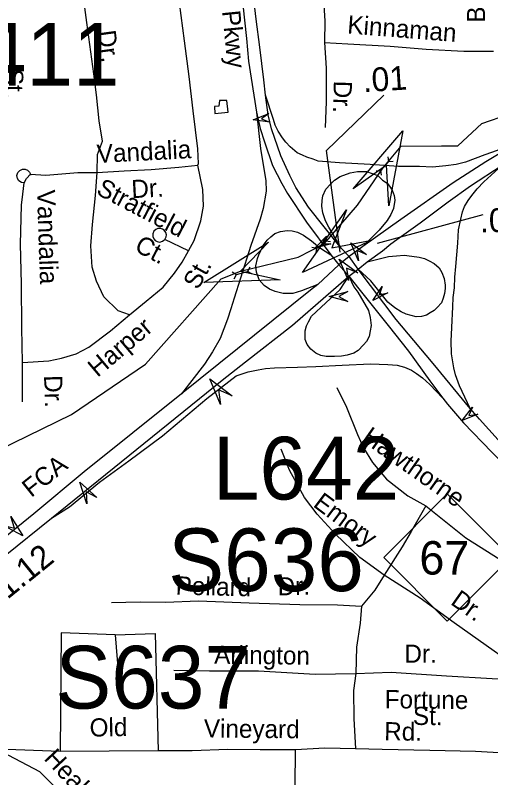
# Model space of a CAD drawing. Extents: x 1547597 to 1699558, y 810033 to 920809.
# Drawn here: x 1612140 to 1614630, y 849367 to 853357 of the extents above; entities that cross this region are included whole.
import ezdxf

# ---------------------------------------------------------------- set-up
doc = ezdxf.new("R2010")
doc.units = 0
for name, color, linetype in [('Exist Hydrographic Creek Single Shore', 7, 'Continuous'), ('Exist Hydrographic Misc Water Feature', 7, 'Continuous'), ('Exist Road Non-System Type 51', 7, 'Continuous'), ('Exist Road Non-System Type 51 Label', 7, 'Continuous'), ('Exist Road Primary Interstate Divided Center Attributed', 7, 'Continuous'), ('Exist Road Primary Interstate Label', 7, 'Continuous'), ('Exist Road Primary Interstate Mileage Hundredths English Label', 7, 'Continuous'), ('Exist Road Primary Interstate Ramp 1 Lane Attributed', 7, 'Continuous'), ('Exist Road Primary Interstate Structure Cantilever Sign Attributed CELL', 7, 'Continuous'), ('Exist Road Primary Interstate Structure Cantilever Sign Number Label', 7, 'Continuous'), ('Exist Road Primary Interstate Structure Ovrhead Sign Attributed CELL', 7, 'Continuous'), ('Exist Road Primary Interstate Structure Ovrhead Sign Number Label', 7, 'Continuous'), ('Exist Road Primary NC Divided Attributed', 7, 'Continuous'), ('Exist Road Primary NC Label', 7, 'Continuous'), ('Exist Road Primary NC Service Mileage Hundredths English Label', 7, 'Continuous'), ('Exist Road Primary NC Shield CELL', 7, 'Continuous'), ('Exist Road Primary NC Shield Number Label', 7, 'Continuous'), ('Exist Road Secondary Structure Culvert Attributed CELL', 7, 'Continuous'), ('Exist Road Secondary Structure Culvert CELL', 7, 'Continuous'), ('Exist Road Secondary Structure Culvert Number Label', 7, 'Continuous'), ('Exist Road Secondary Structure Standard Bridge Attributed CELL', 7, 'Continuous')]:
    doc.layers.add(name, color=color, linetype=linetype)

msp = doc.modelspace()

# ---------------------------------------------------------------- linework, layer by layer
at = {"layer": 'Exist Hydrographic Creek Single Shore'}
msp.add_lwpolyline([(1611594.1, 850857.9), (1612435.7, 851267.3), (1612822.7, 851531.9), (1613218.5, 851977.1), (1613319.3, 852016.9), (1613622.3, 852090.4), (1613757.8, 852160.1), (1613932.3, 852362.2), (1614064.9, 852556.6), (1614161.3, 852672.3), (1614372.7, 852674), (1614458.3, 852674), (1614584.2, 852789.9), (1615148.9, 852985.6), (1615306.6, 853204), (1615898.7, 853406.3), (1616283.8, 853510.1), (1617321.6, 853814.1), (1617885.8, 853975.5), (1618594.7, 854297), (1618697.7, 854345.4)], dxfattribs=at)
at = {"layer": 'Exist Hydrographic Misc Water Feature'}
msp.add_lwpolyline([(1613254.9, 852850.4), (1613248, 852911.2), (1613209.4, 852909.8), (1613207, 852880.6), (1613184.3, 852879.1), (1613185, 852843.4), (1613254.9, 852850.4)], dxfattribs=at)
at = {"layer": 'Exist Road Non-System Type 51'}
for p, q in [((1613048.2, 852123.9), (1612923.5, 852184)), ((1612178.9, 851334.6), (1612178.9, 851540.3))]:
    msp.add_line(p, q, dxfattribs=at)
for points in [[(1612568.7, 852534.1), (1612571.1, 852628.7), (1612597.4, 852697.7), (1612579.3, 852804.2), (1612565.9, 852940.3), (1612551.9, 853050.5), (1612514.9, 853319), (1612472.7, 853633.6), (1612437.8, 853908), (1612402.5, 854158.5), (1612362.1, 854455.1), (1612344.6, 854645.6)], [(1613680.2, 854248.2), (1613697.3, 854054), (1613721.4, 853801.8), (1613750.7, 853491.6), (1613762.2, 853327.5), (1613760.5, 853213.6)], [(1613096.5, 852572.7), (1613100.7, 852580.7), (1613096, 852658.6), (1613071.9, 852857), (1613051.5, 853035.7), (1613026.7, 853223.5), (1613000.3, 853422), (1612976.7, 853660.4), (1612961.3, 853800.6)], [(1613760.5, 853213.6), (1613768.3, 853079.6), (1613767.8, 852903.7), (1613763.7, 852769.9)], [(1613760.5, 853213.6), (1613882.2, 853207.8), (1614103.9, 853194.5), (1614291.5, 853179.7), (1614489.1, 853168.8), (1614645, 853168.5)], [(1612187.6, 852480.5), (1612173, 852481.4), (1612159.8, 852490.6), (1612151.8, 852501.8), (1612149.3, 852517.9), (1612153.4, 852533.4), (1612164.1, 852544.8), (1612177.8, 852550.9), (1612192, 852550.8), (1612205.5, 852545.3), (1612215.1, 852535.5), (1612219.9, 852524.8), (1612220.2, 852519.8)], [(1612568.7, 852534.1), (1612710.3, 852541.8), (1612852.3, 852549.1), (1612996.4, 852562.6), (1613096.5, 852572.7)], [(1613048.2, 852123.9), (1613077.3, 852177.3), (1613113, 852280.4), (1613126.6, 852358.2), (1613122.1, 852444.4), (1613096.5, 852572.7)], [(1612187.6, 852480.5), (1612200, 852503.4), (1612219.9, 852524.8)], [(1612219.9, 852524.8), (1612300.4, 852519.5), (1612468.4, 852534.3), (1612568.7, 852534.1)], [(1612738.4, 851789.8), (1612679.8, 851810.3), (1612603.5, 851883.5), (1612565.1, 851966.1), (1612542.8, 852038.3), (1612537.1, 852150.3), (1612544.8, 852261.5), (1612561.5, 852413.2), (1612568.7, 852534.1)], [(1612178.9, 851540.3), (1612175.3, 851720.7), (1612172.4, 851950.9), (1612167.7, 852159.8), (1612173.5, 852363), (1612180.3, 852420.9), (1612187.6, 852480.5)], [(1612923.5, 852184), (1612927.2, 852189.8), (1612930.8, 852197.9), (1612931.6, 852208.5), (1612928.7, 852220.8), (1612920.9, 852231.7), (1612911.6, 852238.1), (1612901.1, 852241.7), (1612886.7, 852240.8), (1612876.4, 852235.8), (1612866.6, 852227), (1612860.9, 852213.3), (1612860.6, 852199.9), (1612865.6, 852187.2), (1612873.2, 852178.7), (1612883.9, 852172.2), (1612897.8, 852170.3), (1612910.9, 852173.9), (1612919.2, 852179.1), (1612923.5, 852184)], [(1612738.4, 851789.8), (1612825.5, 851860), (1612914.9, 851934.3), (1612974.2, 852007.3), (1613015.2, 852064.5), (1613048.2, 852123.9)], [(1612178.9, 851540.3), (1612315.8, 851548.7), (1612382, 851562.9), (1612458.9, 851584.9), (1612525.5, 851619.8), (1612638.9, 851705.5), (1612738.4, 851789.8)], [(1613824.7, 851408.5), (1613874.8, 851305.7), (1613932.2, 851162.6), (1613964.8, 851094.1), (1614011.1, 851017.3), (1614083.7, 850930.2), (1614196.1, 850843.1), (1614289.6, 850789.6)], [(1614072.1, 850427.3), (1613944.1, 850519.2), (1613817.9, 850641.9), (1613720.5, 850746.5), (1613655.6, 850833.1), (1613576.3, 850977.4), (1613533, 851085.7)], [(1614289.6, 850789.6), (1614213.4, 850655.3), (1614166.4, 850576.1), (1614072.1, 850427.3)], [(1614289.6, 850789.6), (1614499.9, 850622.6), (1614679.1, 850508.9), (1614923.7, 850344.4), (1615083.8, 850219.7)], [(1614072.1, 850427.3), (1614022.9, 850349.3), (1613953.4, 850264.5)], [(1614855.5, 849882.8), (1614648.3, 850030.5), (1614439.2, 850178.2), (1614260.7, 850307.5), (1614072.1, 850427.3)], [(1612645.3, 850284.4), (1612795.2, 850287.6), (1612926.8, 850285.3), (1613100.8, 850293.2), (1613365.5, 850282.3), (1613630, 850274.4), (1613827.7, 850272.8), (1613953.4, 850264.5)], [(1613953.4, 850264.5), (1613945.8, 850176.8), (1613927.4, 850051.1), (1613923, 849913.3)], [(1612380.1, 850126.2), (1612376.5, 849505.5)], [(1612663, 850115.3), (1612380.1, 850126.2)], [(1612663, 850115.3), (1612873.3, 850122.6)], [(1612663, 850115.3), (1612681.1, 849901.2)], [(1612873.3, 850122.6), (1612888.7, 849508.1)], [(1612970.2, 849930.2), (1613157.8, 849926.9), (1613413.5, 849926.1), (1613711, 849909.2), (1613923, 849913.3)], [(1613923, 849913.3), (1613911.4, 849823.5), (1613912.6, 849677.6), (1613921.6, 849519.5)], [(1613923, 849913.3), (1614108.9, 849919.9), (1614398.5, 849901), (1614637.9, 849886.4), (1614855.5, 849882.8)], [(1611909.7, 849523), (1612105.3, 849484.7), (1612266.9, 849399.5), (1612424.2, 849242.1), (1612589.7, 849074.1)], [(1612376.5, 849505.5), (1611909.7, 849523)], [(1613607.9, 849513.1), (1613423.5, 849512.8), (1613253.4, 849514.7), (1613066.1, 849508.1), (1612888.7, 849508.1)], [(1613616.3, 848999.2), (1613606.9, 849135.3), (1613606.3, 849323.2), (1613607.9, 849513.1)], [(1613921.6, 849519.5), (1613761.8, 849522.4), (1613607.9, 849513.1)], [(1615139.8, 849441.5), (1615073.2, 849463.1), (1615051.3, 849474.8), (1614934, 849486.3), (1614796.8, 849491.6), (1614550.7, 849503.9), (1614311.1, 849510.4), (1614061.4, 849514.9), (1613921.6, 849519.5)], [(1612888.7, 849508.1), (1612376.5, 849505.5)]]:
    msp.add_lwpolyline(points, dxfattribs=at)
at = {"layer": 'Exist Road Primary Interstate Divided Center Attributed'}
for points in [[(1614990.7, 852819.7), (1614604, 852590), (1614433.5, 852479), (1614160, 852287.2), (1613959.7, 852146)], [(1613983, 852066.1), (1614062.6, 852124.5), (1614107.8, 852160.5), (1614137.7, 852183.6), (1614260.8, 852270), (1614407.1, 852380.7), (1614524.1, 852463.9), (1614690.2, 852571.5)], [(1613959.7, 852146), (1613888.2, 852094.4)], [(1613888.2, 852094.4), (1613834.3, 852051.2)], [(1613936.5, 852028), (1613983, 852066.1)], [(1613834.3, 852051.2), (1613724, 851947.1)], [(1613886.3, 851991.7), (1613936.5, 852028)], [(1612330.6, 850725.5), (1613224.7, 851447.9), (1613346.8, 851542.9), (1613591.4, 851734.7), (1613886.3, 851991.7)], [(1613724, 851947.1), (1613686.7, 851918.9), (1613010.2, 851375.8)], [(1613010.2, 851375.8), (1612501.3, 850967.3), (1612238.6, 850748.3), (1611807.5, 850398.9), (1611455.2, 850113.6), (1611165.3, 849893.8), (1610880.9, 849686.6)], [(1609818, 848863.7), (1610951.8, 849650.5), (1611075.2, 849735.8), (1611208.1, 849832), (1611360.5, 849948.2), (1611508.2, 850064.4), (1611742.4, 850253.5), (1612088.1, 850529.5), (1612330.6, 850725.5)]]:
    msp.add_lwpolyline(points, dxfattribs=at)
at = {"layer": 'Exist Road Primary Interstate Mileage Hundredths English Label'}
msp.add_lwpolyline([(1613841.6, 852117.4), (1613770.3, 852649.7), (1614070.2, 852938.4)], dxfattribs=at)
at = {"layer": 'Exist Road Primary Interstate Ramp 1 Lane Attributed'}
for points in [[(1614990.7, 852819.7), (1614663.6, 852648.7), (1614599.9, 852627.1), (1614498.7, 852588.7), (1614450, 852575.6), (1614395.6, 852568.1), (1614324.4, 852562.5), (1614256.7, 852564.9), (1614147.1, 852564.9), (1613998.1, 852575.2), (1613838.8, 852585.1), (1613726.5, 852593.4), (1613700.4, 852603.7), (1613667, 852613.9), (1613643.8, 852624.1), (1613616.8, 852637.1), (1613580.6, 852667.8), (1613557.3, 852692.9), (1613539.7, 852716.1), (1613516.4, 852749.6), (1613500.6, 852782.1), (1613493.2, 852810.9), (1613450.5, 852939.1)], [(1613404, 852849), (1613424.4, 852659.4), (1613442.1, 852553.5), (1613452.3, 852492.2), (1613455.1, 852435.5), (1613439.3, 852346.3), (1613423.5, 852290), (1613373.5, 852152.1), (1613320.1, 851980.6), (1613286.4, 851876.6), (1613269.6, 851820.4), (1613252.7, 851767), (1613233.1, 851716.4), (1613213.4, 851665.8), (1613174.1, 851595.5), (1613131.9, 851530.8), (1613010.2, 851375.8)], [(1614522.4, 851299.9), (1614466.2, 851418.6), (1614445.7, 851474.8), (1614436.9, 851512), (1614425.3, 851584.9), (1614423, 851653.9), (1614424.4, 851686.9), (1614426.7, 851723.6), (1614431, 851830.6), (1614433.4, 851880.4), (1614440.5, 851930.2), (1614442.8, 851987.1), (1614447.6, 852041.6), (1614457, 852164.8), (1614461.8, 852233.6), (1614473.6, 852290.4), (1614483.1, 852328.4), (1614492.6, 852356.8), (1614511.5, 852387.6), (1614530.5, 852413.7), (1614558.9, 852449.2), (1614594.4, 852484.8), (1614690.2, 852571.5)], [(1613847.3, 852137.2), (1613783.2, 852247.7), (1613764.6, 852280.3), (1613750.7, 852322.7), (1613745, 852358.3), (1613746.9, 852388.1), (1613750.7, 852412.6), (1613767.1, 852446.9), (1613790.3, 852473.6), (1613812, 852493.1), (1613842.6, 852513.5), (1613893.7, 852532.1), (1613931.8, 852538.6), (1613979.2, 852538.6), (1614038.7, 852518.2), (1614063.8, 852493.1), (1614087, 852477.3), (1614100, 852462.4), (1614114.9, 852442), (1614125.1, 852414.1), (1614127.9, 852389), (1614120.5, 852345.3), (1614107.5, 852314.7), (1614088, 852283.1), (1614046.5, 852231.5), (1613959.7, 852146)], [(1613724, 851947.1), (1613638.8, 851914), (1613594.4, 851900.7), (1613542.8, 851901.1), (1613501.2, 851911.1), (1613471.1, 851924), (1613443.7, 851943.6), (1613418.5, 851973.1), (1613403.7, 852013), (1613400.8, 852046.4), (1613408.4, 852083.4), (1613416.6, 852103.3), (1613426.6, 852126.3), (1613441, 852153.6), (1613459.6, 852179.4), (1613478.2, 852198), (1613499.8, 852215.3), (1613529.9, 852225.3), (1613564.3, 852231), (1613590.1, 852228.2), (1613618.8, 852221), (1613650.3, 852205.2), (1613691.9, 852176.5), (1613733.5, 852140.7), (1613793.4, 852102.8)], [(1613983, 852066.1), (1614059.1, 852086.6), (1614094.6, 852093.7), (1614137.3, 852098.5), (1614177.5, 852100.8), (1614217.8, 852096.1), (1614255.7, 852091.4), (1614284.1, 852084.2), (1614307.8, 852072.4), (1614333.9, 852058.2), (1614359.9, 852034.5), (1614374.1, 852010.8), (1614386, 851980), (1614392.1, 851943.8), (1614390.7, 851927.8), (1614388.3, 851901.7), (1614381.2, 851875.7), (1614371.8, 851852), (1614350.4, 851828.3), (1614333.9, 851811.7), (1614312.6, 851799.8), (1614293.6, 851788), (1614267.5, 851780.9), (1614239.1, 851778.5), (1614214.3, 851785.7), (1614187.4, 851792.2), (1614161.8, 851804.7), (1614128.4, 851825.1), (1614091.7, 851855.8), (1614001.5, 851966.6), (1613936.5, 852028)], [(1613886.3, 851991.7), (1613912.8, 851935.6), (1613933.7, 851907.2), (1613989.5, 851811.4), (1613999.7, 851774.7), (1614003.9, 851733.8), (1613999.7, 851705.5), (1613993.6, 851676.7), (1613979.2, 851649.3), (1613964.8, 851631.9), (1613936.4, 851603.5), (1613912.8, 851588.4), (1613877.9, 851578.9), (1613849.6, 851572.8), (1613812.4, 851571.4), (1613768.1, 851571.6), (1613739.8, 851576.9), (1613715, 851589.3), (1613688.4, 851608.8), (1613668.9, 851633.6), (1613658.3, 851660.2), (1613658.3, 851685), (1613658.3, 851706.3), (1613665.4, 851731.1), (1613676, 851752.4), (1613691.9, 851782.5), (1613842.6, 851921.6), (1613886.3, 851991.7)], [(1612330.6, 850725.5), (1612424.5, 850784.1), (1612582.5, 850913.7), (1612735.8, 851026.2), (1612911.5, 851155.4), (1613143.8, 851351), (1613297.1, 851470.7), (1613360.4, 851491.1), (1613412.5, 851502.3), (1613451.5, 851507.9), (1613498, 851511.6), (1613617.8, 851514.9), (1613713.9, 851519.1), (1613851.6, 851526.5), (1614000.4, 851532.1), (1614091.6, 851530.2), (1614139.9, 851526.5), (1614179, 851515.3), (1614214.4, 851500.4), (1614242.3, 851481.8), (1614272, 851459.5), (1614311.1, 851424.1), (1614379.4, 851353.8)]]:
    msp.add_lwpolyline(points, dxfattribs=at)
at = {"layer": 'Exist Road Primary Interstate Structure Cantilever Sign Attributed CELL'}
msp.add_lwpolyline([(1613882.3, 851859.2), (1613783.4, 851885.7), (1613882.3, 851912.2), (1613834.6, 851885.7)], close=True, dxfattribs=at)
at = {"layer": 'Exist Road Primary Interstate Structure Ovrhead Sign Attributed CELL'}
for points in [[(1613473.6, 852797.6), (1613386.5, 852809), (1613467.6, 852842.6), (1613430, 852814.8)], [(1613793.2, 852161.4), (1613708.7, 852137.5), (1613769.9, 852200.4), (1613746.4, 852160)], [(1613938.6, 852072.6), (1613898.1, 852166.6), (1613980.2, 852105.4), (1613929.8, 852126.4)], [(1614091.9, 851903.7), (1614013.3, 851864.7), (1614061.9, 851937.8), (1614046.2, 851893.7)], [(1613216, 851319.7), (1613159.8, 851454.8), (1613276, 851365.9), (1613204.4, 851396.8)], [(1614562.4, 851269.8), (1614480.9, 851237.1), (1614535.1, 851306.2), (1614516.1, 851263.4)], [(1612514.7, 850800.3), (1612479.1, 850914.3), (1612566.9, 850833.4), (1612511, 850863.9)], [(1612117.6, 850734), (1612180.6, 850632.4), (1612075.3, 850688.9), (1612137, 850673.3)]]:
    msp.add_lwpolyline(points, close=True, dxfattribs=at)
at = {"layer": 'Exist Road Primary NC Divided Attributed'}
for points in [[(1613450.5, 852939.1), (1613441.8, 853019.5), (1613421.3, 853190.3), (1613401.4, 853336.9), (1613358.2, 853706.1), (1613328.4, 853916.6), (1613307.9, 854130.6), (1613282.4, 854315.6), (1613251.2, 854584.8), (1613209.4, 854809.5), (1613142.8, 855066.7)], [(1613098.8, 855048.3), (1613167.6, 854798.8), (1613210.1, 854574.9), (1613242, 854273), (1613269.6, 853990.3), (1613298, 853686.3), (1613331.3, 853410.6), (1613351.1, 853234.2), (1613361, 853116.6), (1613404, 852849)], [(1613847.3, 852137.2), (1613676.3, 852352.8), (1613609.4, 852455.9), (1613577.8, 852518.6), (1613531.3, 852621.8), (1613483, 852762.6), (1613465.3, 852836), (1613450.5, 852939.1)], [(1613404, 852849), (1613422.6, 852764.4), (1613444.9, 852693.8), (1613487.6, 852570.7), (1613536, 852475.9), (1613565.7, 852424.3), (1613665.1, 852273.8), (1613793.4, 852102.8)], [(1613793.4, 852102.8), (1613834.3, 852051.2)], [(1613888.2, 852094.4), (1613847.3, 852137.2)], [(1613936.5, 852028), (1613888.2, 852094.4)], [(1613834.3, 852051.2), (1613886.3, 851991.7)], [(1614522.4, 851299.9), (1614328.2, 851533.8), (1614227.4, 851655.3), (1614134.4, 851765.4), (1613936.5, 852028)], [(1613886.3, 851991.7), (1613940.2, 851925.3), (1614092.6, 851732.7), (1614199.9, 851600), (1614311.8, 851443.9), (1614379.4, 851353.8)], [(1614379.4, 851353.8), (1614403.8, 851321.2), (1614487, 851224.7), (1614635.3, 851071), (1614786.3, 850921.2), (1614859.9, 850845.4)], [(1614916, 850884), (1614835.6, 850964.6), (1614669.2, 851135.6), (1614571.7, 851243.6), (1614522.4, 851299.9)]]:
    msp.add_lwpolyline(points, dxfattribs=at)
at = {"layer": 'Exist Road Primary NC Service Mileage Hundredths English Label'}
msp.add_line((1614036.5, 852164.3), (1614591.3, 852314.2), dxfattribs=at)
at = {"layer": 'Exist Road Primary NC Shield CELL'}
msp.add_lwpolyline([(1614069.6, 850520.1), (1614402.6, 850853.1), (1614735.6, 850520.1), (1614402.6, 850187.1)], close=True, dxfattribs=at)
at = {"layer": 'Exist Road Secondary Structure Culvert Attributed CELL'}
for points in [[(1613910, 852448), (1614169.6, 852752.3), (1614096.9, 852359), (1614083.6, 852571.8)], [(1614007.3, 852180.6), (1613644.8, 852011.6), (1613874.3, 852339.2), (1613798, 852140.2)], [(1613527.8, 851972.2), (1613128, 851958.6), (1613467.4, 852170.3), (1613319.3, 852016.9)]]:
    msp.add_lwpolyline(points, close=True, dxfattribs=at)
at = {"layer": 'Exist Road Secondary Structure Culvert CELL'}
for p, q in [((1614055.2, 852544.6), (1614094.6, 852590.5)), ((1614091.9, 852615.8), (1614094.6, 852590.5)), ((1614119.9, 852591.8), (1614094.6, 852590.5)), ((1614029.9, 852543.3), (1614055.2, 852544.6)), ((1614057.9, 852519.3), (1614055.2, 852544.6)), ((1613769.6, 852200.7), (1613766.9, 852175.5)), ((1613693.8, 852142.9), (1613718.8, 852138.8)), ((1613718.8, 852138.8), (1613766.9, 852175.5)), ((1613792, 852171.4), (1613766.9, 852175.5)), ((1613716.1, 852113.6), (1613718.8, 852138.8)), ((1613369, 852038.6), (1613357, 852016.3)), ((1613277, 852013.5), (1613298.6, 852000.3)), ((1613286.7, 851978), (1613298.6, 852000.3)), ((1613298.6, 852000.3), (1613357, 852016.3)), ((1613378.7, 852003.1), (1613357, 852016.3))]:
    msp.add_line(p, q, dxfattribs=at)
at = {"layer": 'Exist Road Secondary Structure Standard Bridge Attributed CELL'}
msp.add_lwpolyline([(1613885.9, 851969.7), (1613836.1, 852081), (1613934.9, 852009.5), (1613874.6, 852033.7)], close=True, dxfattribs=at)

# ---------------------------------------------------------------- texts
at = {"layer": 'Exist Road Non-System Type 51 Label'}
for s, rotation, p in [('Burkwood', 89.1425, (1614600, 853317.2)), ('Kinnaman', 355.4853, (1613876.9, 853261.8)), ('Dr.', 277.8409, (1612571, 853272.2)), ('St.', 270.7297, (1612086.9, 853075.3)), ('Dr.', 268.2931, (1613809.1, 853015.3)), ('Vandalia', 2.9529, (1612570.1, 852583.8)), ('Stratfield', 332.3389, (1612559, 852423.5)), ('Dr.', 2.9529, (1612750.8, 852399.4)), ('Vandalia', 271.8778, (1612254.2, 852442.5)), ('Ct.', 332.3389, (1612759.5, 852126.3)), ('St.', 60.9145, (1613097.4, 851915.8)), ('Harper', 40.2315, (1612570.9, 851459.1)), ('Dr.', 271.7738, (1612291.1, 851472.2)), ('Hawthorne', 324.7862, (1613949.5, 851131.7)), ('Emory', 323.1796, (1613695.1, 850789.9)), ('Pollard', 358.5216, (1612979.5, 850326.3)), ('Dr.', 1.3994, (1613515.2, 850320.9)), ('Dr.', 324.7622, (1614414.8, 850278.4)), ('Arlington', 359.3776, (1613181.7, 849964.2)), ('Dr.', 359.9199, (1614178, 849969.1)), ('Fortune', 359.3776, (1614074.6, 849731.3)), ('St.', 359.3776, (1614222.3, 849644)), ('Old', 0.8599, (1612530.5, 849582.6)), ('Vineyard', 359.4445, (1613127.8, 849578.4)), ('Rd.', 358.9753, (1614071.8, 849563.9)), ('Healy', 312.9895, (1612286.5, 849465.2))]:
    msp.add_text(s, height=95, rotation=rotation, dxfattribs=at).set_placement(p)
at = {"layer": 'Exist Road Primary Interstate Label'}
msp.add_text('FCA', height=95, rotation=38.7269, dxfattribs=at).set_placement((1612224.4, 850830.6))
at = {"layer": 'Exist Road Primary Interstate Mileage Hundredths English Label'}
for s, rotation, p in [('.01', 3.6706, (1613963.7, 852953.5)), ('1.12', 38.9531, (1612099.7, 850297.7))]:
    msp.add_text(s, height=125, rotation=rotation, dxfattribs=at).set_placement(p)
at = {"layer": 'Exist Road Primary Interstate Structure Cantilever Sign Number Label'}
msp.add_text('L642', height=328.08, dxfattribs=at).set_placement((1613175.4, 850823))
at = {"layer": 'Exist Road Primary Interstate Structure Ovrhead Sign Number Label'}
for s, p in [('S636', (1612941.4, 850343.9)), ('S637', (1612350.4, 849729.4))]:
    msp.add_text(s, height=328.08, dxfattribs=at).set_placement(p)
at = {"layer": 'Exist Road Primary NC Label'}
msp.add_text('Pkwy', height=95, rotation=275.6328, dxfattribs=at).set_placement((1613223.3, 853378.1))
at = {"layer": 'Exist Road Primary NC Service Mileage Hundredths English Label'}
msp.add_text('.02', height=125, rotation=0.8098, dxfattribs=at).set_placement((1614574.6, 852220.7))
at = {"layer": 'Exist Road Primary NC Shield Number Label'}
msp.add_text('67', height=175, dxfattribs=at).set_placement((1614256.8, 850430.4))
at = {"layer": 'Exist Road Secondary Structure Culvert Number Label'}
msp.add_text('C411', height=328.08, dxfattribs=at).set_placement((1611637.8, 852988.6))

doc.saveas('drawing.dxf')
